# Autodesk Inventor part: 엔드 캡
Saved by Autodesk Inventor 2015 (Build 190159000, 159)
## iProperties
Created: 2026-05
Part Number: 엔드 캡
Material: 일반
Document SubType Name: Modeling
Designer: 104
Density: 1 g/cm^3
Appearance: 기본값
Author: 104
Author: jhkim
Creation Date: 2026-04-27
Sending System: Autodesk Inventor 2027
Preprocessor: ST-DEVELOPER v20.1
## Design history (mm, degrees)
node "엔드 캡1"
node "솔리드1"
node "기준1"
